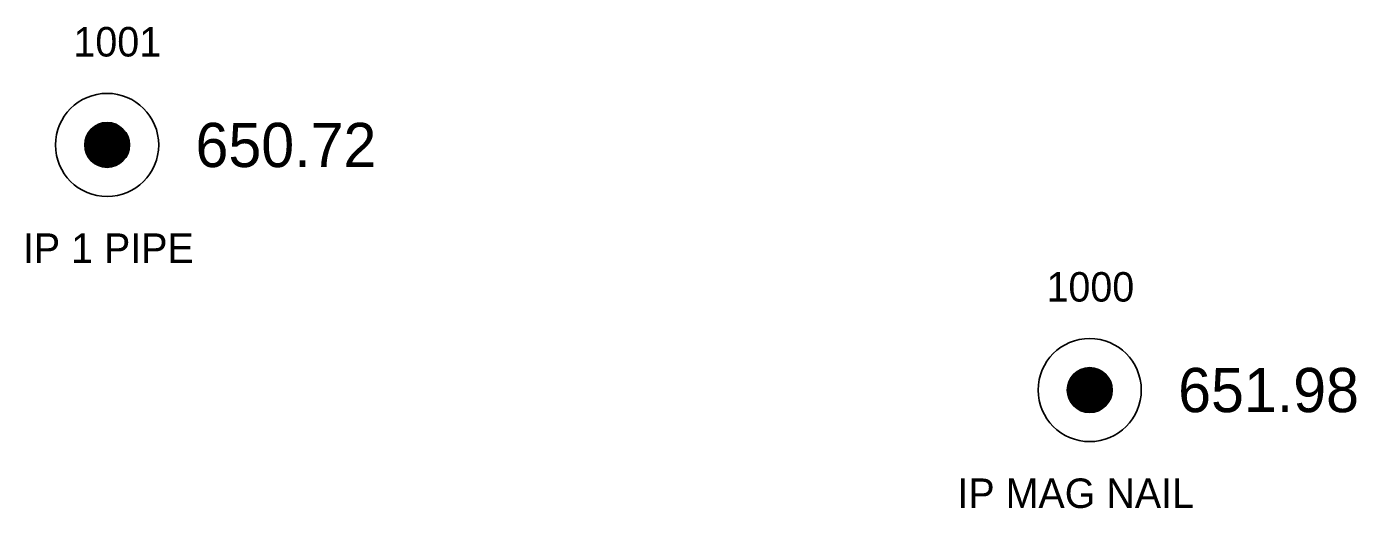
# Model space of a CAD drawing. Extents: x 1694813 to 1696862, y 1086485 to 1091027.
# Drawn here: x 1695310.41 to 1695355.53, y 1086484.65 to 1086501 of the extents above; entities that cross this region are included whole.
import ezdxf

# ---------------------------------------------------------------- set-up
doc = ezdxf.new("R2010")
doc.units = 0
for name, color, linetype in [('RD_EX_DV_Prop_txCode', 7, 'Continuous'), ('RD_EX_DV_PropPin', 7, 'Continuous'), ('RD_EX_TX_DV_Prop_ELEV', 7, 'Continuous'), ('RD_SMD_Locator', 7, 'Continuous')]:
    doc.layers.add(name, color=color, linetype=linetype)

msp = doc.modelspace()

# ---------------------------------------------------------------- linework, layer by layer
at = {"layer": 'RD_EX_DV_PropPin'}
for p, q in [((1695312.723, 1086496.346), (1695312.723, 1086497.615)), ((1695312.758, 1086496.324), (1695312.758, 1086497.637)), ((1695312.793, 1086496.305), (1695312.793, 1086497.656)), ((1695312.828, 1086496.288), (1695312.828, 1086497.674)), ((1695312.863, 1086496.273), (1695312.863, 1086497.688)), ((1695312.898, 1086496.26), (1695312.898, 1086497.701)), ((1695312.933, 1086496.249), (1695312.933, 1086497.712)), ((1695312.968, 1086496.24), (1695312.968, 1086497.721)), ((1695313.003, 1086496.233), (1695313.003, 1086497.729)), ((1695313.038, 1086496.227), (1695313.038, 1086497.735)), ((1695313.073, 1086496.223), (1695313.073, 1086497.739)), ((1695313.108, 1086496.221), (1695313.108, 1086497.741)), ((1695313.143, 1086496.22), (1695313.143, 1086497.742)), ((1695313.178, 1086496.221), (1695313.178, 1086497.741)), ((1695313.213, 1086496.223), (1695313.213, 1086497.739)), ((1695313.248, 1086496.227), (1695313.248, 1086497.735)), ((1695313.283, 1086496.233), (1695313.283, 1086497.729)), ((1695313.318, 1086496.24), (1695313.318, 1086497.721)), ((1695313.353, 1086496.249), (1695313.353, 1086497.712)), ((1695313.388, 1086496.26), (1695313.388, 1086497.701)), ((1695313.423, 1086496.273), (1695313.423, 1086497.688)), ((1695313.458, 1086496.288), (1695313.458, 1086497.674)), ((1695313.493, 1086496.305), (1695313.493, 1086497.656)), ((1695313.528, 1086496.324), (1695313.528, 1086497.637)), ((1695313.563, 1086496.346), (1695313.563, 1086497.615)), ((1695312.407, 1086496.785), (1695312.407, 1086497.177)), ((1695312.442, 1086496.683), (1695312.442, 1086497.279)), ((1695312.478, 1086496.611), (1695312.478, 1086497.35)), ((1695312.513, 1086496.554), (1695312.513, 1086497.407)), ((1695312.548, 1086496.507), (1695312.548, 1086497.455)), ((1695312.583, 1086496.466), (1695312.583, 1086497.496)), ((1695312.618, 1086496.43), (1695312.618, 1086497.532)), ((1695312.653, 1086496.399), (1695312.653, 1086497.563)), ((1695312.688, 1086496.371), (1695312.688, 1086497.591)), ((1695313.598, 1086496.371), (1695313.598, 1086497.591)), ((1695313.633, 1086496.399), (1695313.633, 1086497.563)), ((1695313.668, 1086496.43), (1695313.668, 1086497.532)), ((1695313.703, 1086496.466), (1695313.703, 1086497.496)), ((1695313.738, 1086496.507), (1695313.738, 1086497.455)), ((1695313.773, 1086496.554), (1695313.773, 1086497.407)), ((1695313.808, 1086496.611), (1695313.808, 1086497.35)), ((1695313.843, 1086496.683), (1695313.843, 1086497.279)), ((1695313.878, 1086496.785), (1695313.878, 1086497.177)), ((1695345.814, 1086488.298), (1695345.814, 1086489.037)), ((1695345.849, 1086488.241), (1695345.849, 1086489.094)), ((1695345.884, 1086488.193), (1695345.884, 1086489.142)), ((1695345.919, 1086488.153), (1695345.919, 1086489.183)), ((1695345.954, 1086488.117), (1695345.954, 1086489.218)), ((1695345.989, 1086488.085), (1695345.989, 1086489.25)), ((1695346.024, 1086488.058), (1695346.024, 1086489.277)), ((1695346.059, 1086488.033), (1695346.059, 1086489.302)), ((1695346.094, 1086488.011), (1695346.094, 1086489.324)), ((1695346.129, 1086487.992), (1695346.129, 1086489.343)), ((1695346.164, 1086487.975), (1695346.164, 1086489.36)), ((1695346.199, 1086487.96), (1695346.199, 1086489.375)), ((1695346.234, 1086487.947), (1695346.234, 1086489.388)), ((1695346.269, 1086487.936), (1695346.269, 1086489.399)), ((1695346.304, 1086487.927), (1695346.304, 1086489.408)), ((1695346.339, 1086487.92), (1695346.339, 1086489.416)), ((1695346.374, 1086487.914), (1695346.374, 1086489.421)), ((1695346.409, 1086487.91), (1695346.409, 1086489.425)), ((1695346.444, 1086487.907), (1695346.444, 1086489.428)), ((1695346.479, 1086487.907), (1695346.479, 1086489.429)), ((1695346.514, 1086487.907), (1695346.514, 1086489.428)), ((1695346.549, 1086487.91), (1695346.549, 1086489.425)), ((1695346.584, 1086487.914), (1695346.584, 1086489.421)), ((1695346.619, 1086487.92), (1695346.619, 1086489.416)), ((1695346.654, 1086487.927), (1695346.654, 1086489.408)), ((1695346.689, 1086487.936), (1695346.689, 1086489.399)), ((1695346.724, 1086487.947), (1695346.724, 1086489.388)), ((1695346.759, 1086487.96), (1695346.759, 1086489.375)), ((1695346.794, 1086487.975), (1695346.794, 1086489.36)), ((1695346.829, 1086487.992), (1695346.829, 1086489.343)), ((1695346.864, 1086488.011), (1695346.864, 1086489.324)), ((1695346.899, 1086488.033), (1695346.899, 1086489.302)), ((1695346.934, 1086488.058), (1695346.934, 1086489.277)), ((1695346.969, 1086488.085), (1695346.969, 1086489.25)), ((1695347.004, 1086488.117), (1695347.004, 1086489.218)), ((1695347.039, 1086488.153), (1695347.039, 1086489.183)), ((1695347.074, 1086488.193), (1695347.074, 1086489.142)), ((1695347.109, 1086488.241), (1695347.109, 1086489.094)), ((1695347.144, 1086488.298), (1695347.144, 1086489.037)), ((1695345.744, 1086488.471), (1695345.744, 1086488.864)), ((1695345.779, 1086488.37), (1695345.779, 1086488.966)), ((1695347.179, 1086488.37), (1695347.179, 1086488.966)), ((1695347.214, 1086488.471), (1695347.214, 1086488.864))]:
    msp.add_line(p, q, dxfattribs=at)
for centre, radius in [((1695313.143, 1086496.981), 1.75), ((1695313.143, 1086496.981), 0.761), ((1695346.479, 1086488.668), 1.75), ((1695346.479, 1086488.668), 0.761)]:
    msp.add_circle(centre, radius, dxfattribs=at)
at = {"layer": 'RD_SMD_Locator'}
for centre in [(1695313.143, 1086496.981), (1695346.479, 1086488.668)]:
    msp.add_circle(centre, 0.15, dxfattribs=at)

# ---------------------------------------------------------------- texts
at = {"layer": 'RD_EX_DV_Prop_txCode'}
for s, p in [('1001', (1695312.001, 1086499.981)), ('IP 1 PIPE', (1695310.288, 1086492.981)), ('1000', (1695345.014, 1086491.668)), ('IP MAG NAIL', (1695341.991, 1086484.668))]:
    msp.add_text(s, height=1, dxfattribs=at).set_placement(p)
at = {"layer": 'RD_EX_TX_DV_Prop_ELEV'}
for s, p in [('650.72', (1695316.143, 1086496.231)), ('651.98', (1695349.479, 1086487.918))]:
    msp.add_text(s, height=1.5, dxfattribs=at).set_placement(p)

doc.saveas('drawing.dxf')
